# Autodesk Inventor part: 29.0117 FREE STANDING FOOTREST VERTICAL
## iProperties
Created: 2007-06
Part Number: 29.0117 FREE STANDING FOOTREST VERTICAL
Material: Aluminum-6061
Document SubType Name: Modeling
Designer: Andy Moles
Density: 2.71 g/cm^3
Author: Andy Moles
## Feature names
1. Extrusion1
